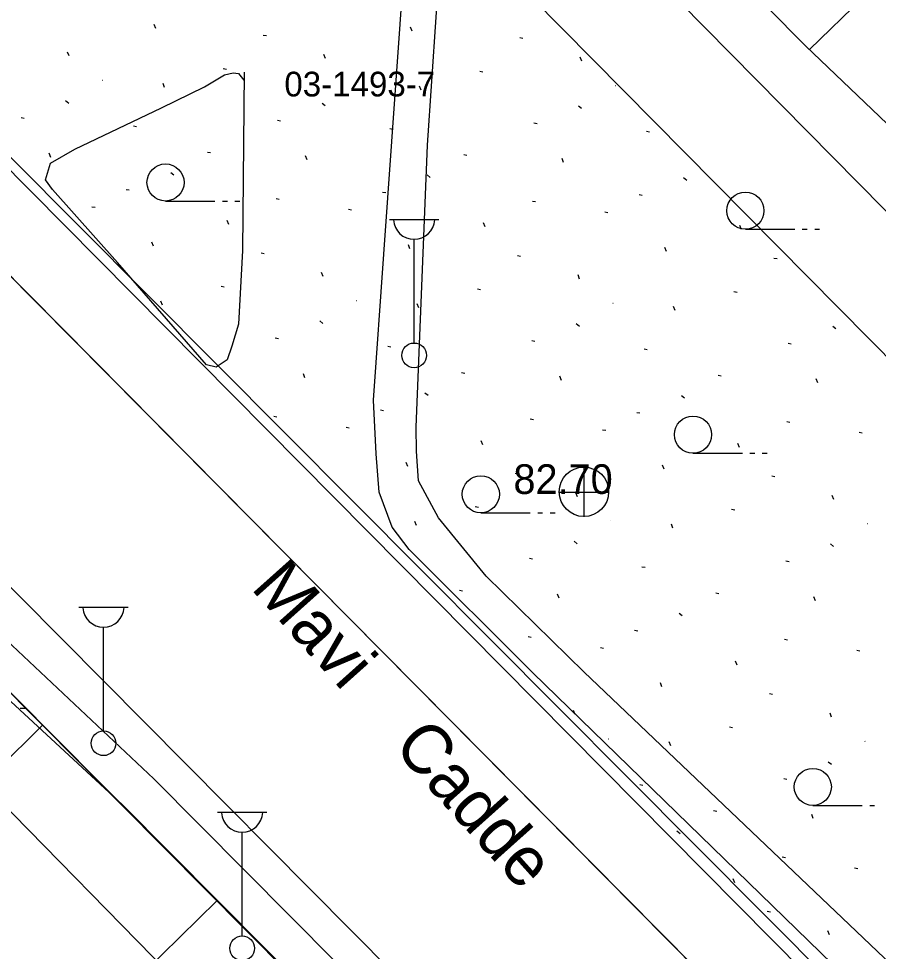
# Model space of a CAD drawing. Extents: x 412225 to 413380, y 4456471 to 4457189.
# Drawn here: x 412345.47 to 412380.23, y 4456938.52 to 4456976.23 of the extents above; entities that cross this region are included whole.
import ezdxf

# ---------------------------------------------------------------- set-up
doc = ezdxf.new("R2010")
doc.units = 0
for name, color, linetype in [('0_HALİHAZIR', 7, 'Continuous'), ('0_KADASTRO', 7, 'Continuous'), ('ADA_KOCEPHE', 7, 'Continuous'), ('Default', 7, 'Continuous'), ('KALDIRIM', 7, 'Continuous'), ('Level 41', 7, 'Continuous'), ('PL_ORGANIZE_SANAYI', 7, 'Continuous')]:
    doc.layers.add(name, color=color, linetype=linetype)

msp = doc.modelspace()

# ---------------------------------------------------------------- linework, layer by layer
at = {"layer": '0_HALİHAZIR'}
for p, q in [((412380.07, 4456977.543), (412377.454, 4456974.98)), ((412351.412, 4456968.858), (412353.412, 4456968.858)), ((412353.712, 4456968.858), (412353.912, 4456968.858)), ((412354.212, 4456968.858), (412354.412, 4456968.858)), ((412360.463, 4456968.117), (412362.463, 4456968.117)), ((412374.857, 4456967.717), (412376.857, 4456967.716)), ((412377.157, 4456967.716), (412377.357, 4456967.716)), ((412377.657, 4456967.716), (412377.857, 4456967.716)), ((412361.463, 4456963.117), (412361.463, 4456967.31)), ((412372.737, 4456958.662), (412374.737, 4456958.662)), ((412375.037, 4456958.662), (412375.237, 4456958.662)), ((412375.537, 4456958.662), (412375.737, 4456958.662)), ((412368.343, 4456956.092), (412368.343, 4456958.092)), ((412367.323, 4456957.082), (412369.323, 4456957.082)), ((412364.16, 4456956.251), (412366.16, 4456956.251)), ((412366.46, 4456956.251), (412366.66, 4456956.251)), ((412366.96, 4456956.251), (412367.16, 4456956.251)), ((412347.905, 4456952.431), (412349.905, 4456952.431)), ((412348.905, 4456947.431), (412348.905, 4456951.624)), ((412345.535, 4456948.352), (412345.735, 4456948.352)), ((412377.581, 4456944.417), (412379.581, 4456944.416)), ((412379.881, 4456944.416), (412380.081, 4456944.416)), ((412353.511, 4456944.141), (412355.511, 4456944.141)), ((412354.511, 4456939.141), (412354.511, 4456943.334))]:
    msp.add_line(p, q, dxfattribs=at)
for points in [[(412364.559, 4456988.91), (412369.327, 4456983.178), (412377.302, 4456975.126), (412390.738, 4456962.288), (412409.437, 4456942.493), (412422.613, 4456929.438), (412434.169, 4456915.9), (412443.007, 4456906.151), (412446.303, 4456903.127)], [(412383.58, 4456935.283), (412368.344, 4456949.804), (412364.375, 4456953.69), (412362.451, 4456956.045), (412361.64, 4456957.546), (412361.556, 4456958.744), (412361.542, 4456959.714), (412362, 4456971.111), (412362.878, 4456984.076)], [(412360.234, 4456966.706), (412361.066, 4456978.306)], [(412349.473, 4456966.368), (412346.849, 4456969.321), (412346.564, 4456969.711), (412346.768, 4456970.388), (412347.745, 4456970.961), (412351.255, 4456972.623), (412352.985, 4456973.471), (412353.799, 4456973.959), (412354.143, 4456974.046), (412354.357, 4456974.017), (412354.584, 4456973.742)], [(412354.587, 4456974.069), (412354.528, 4456966.853), (412354.358, 4456963.875), (412354.092, 4456962.984), (412353.903, 4456962.439), (412353.463, 4456962.136), (412353.067, 4456962.229), (412349.473, 4456966.368)], [(412385.643, 4456930.935), (412366.267, 4456949.783), (412361.263, 4456954.772), (412360.576, 4456955.666), (412360.046, 4456957.088), (412359.925, 4456958.631), (412359.827, 4456960.8), (412360.234, 4456966.706)], [(412340.461, 4456952.961), (412341.05, 4456953.305), (412341.44, 4456953.425), (412342.012, 4456953.384), (412342.339, 4456953.291), (412342.637, 4456952.986), (412344.981, 4456951.095), (412350.936, 4456945.49), (412360.124, 4456936.229), (412372.807, 4456923.414), (412388.747, 4456907.548), (412394.442, 4456901.858), (412397.039, 4456899.351), (412397.651, 4456898.789), (412397.902, 4456898.401), (412398.005, 4456898.011), (412398.01, 4456897.669), (412397.477, 4456896.209)], [(412340.461, 4456952.961), (412349.671, 4456944.435), (412365.051, 4456928.952), (412385.546, 4456908.406), (412397.477, 4456896.209)]]:
    msp.add_lwpolyline(points, dxfattribs=at)
for centre, radius in [((412351.412, 4456969.608), 0.75), ((412374.857, 4456968.467), 0.75), ((412361.463, 4456962.617), 0.5), ((412372.737, 4456959.412), 0.75), ((412364.16, 4456957.001), 0.75), ((412368.328, 4456957.1), 1), ((412348.905, 4456946.931), 0.5), ((412377.581, 4456945.167), 0.75), ((412354.511, 4456938.641), 0.5)]:
    msp.add_circle(centre, radius, dxfattribs=at)
for centre in [(412361.463, 4456968.147), (412348.905, 4456952.461), (412354.511, 4456944.171)]:
    msp.add_arc(centre, 0.837, 183.298, 356.9072, dxfattribs=at)
at = {"layer": '0_KADASTRO'}
for points in [[(412245.621, 4457084.985), (412262.788, 4457087.767), (412498.109, 4456849.333), (412486.377, 4456828.685), (412245.456, 4457070.818)], [(412243.099, 4456868.152), (412335.02, 4456959.17), (412405.36, 4456888.28), (412298.9, 4456782.55), (412242.76, 4456838.938)]]:
    msp.add_lwpolyline(points, dxfattribs=at)
at = {"layer": 'ADA_KOCEPHE'}
for p, q in [((412299.933, 4457044.174), (412519.643, 4456821.8)), ((412299.933, 4457044.174), (412507.885, 4456833.7)), ((412494.937, 4456818.806), (412285.694, 4457030.12)), ((412511.712, 4456801.864), (412285.694, 4457030.12)), ((412335.02, 4456959.17), (412405.36, 4456888.28)), ((412335.02, 4456959.17), (412405.36, 4456888.28))]:
    msp.add_line(p, q, dxfattribs=at)
at = {"layer": 'Default'}
for p, q in [((412513.1, 4456772.743), (412245.17, 4457046.214)), ((412242.844, 4456846.156), (412346.444, 4456947.657)), ((412242.679, 4456831.995), (412353.487, 4456940.558))]:
    msp.add_line(p, q, dxfattribs=at)
at = {"layer": 'KALDIRIM'}
msp.add_line((412509.598, 4456799.736), (412281.429, 4457030.164), dxfattribs=at)
for points in [[(412245.253, 4457053.382), (412266.323, 4457032.279), (412337.147, 4456961.286), (412407.492, 4456890.39), (412481.052, 4456815.891), (412505.085, 4456791.687), (412506.388, 4456790.112), (412510.321, 4456783.97), (412512.973, 4456779.772), (412515.575, 4456774.629), (412518.184, 4456768.139), (412527.355, 4456723.622)], [(412492.963, 4456816.536), (412269.398, 4457042.314)], [(412268.299, 4457030.299), (412337.147, 4456961.286), (412407.492, 4456890.39), (412481.052, 4456815.891), (412505.085, 4456791.687), (412506.388, 4456790.112), (412510.321, 4456783.97), (412512.973, 4456779.772), (412515.575, 4456774.629), (412518.037, 4456768.506)]]:
    msp.add_lwpolyline(points, dxfattribs=at)
at = {"layer": 'Level 41'}
for p, q in [((412351.017, 4456975.836), (412350.953, 4456976)), ((412351.017, 4456975.836), (412350.953, 4456976)), ((412361.384, 4456975.73), (412361.321, 4456975.894)), ((412361.384, 4456975.73), (412361.321, 4456975.894)), ((412355.364, 4456975.571), (412355.49, 4456975.546)), ((412355.364, 4456975.571), (412355.49, 4456975.546)), ((412365.732, 4456975.465), (412365.858, 4456975.44)), ((412365.732, 4456975.465), (412365.858, 4456975.44)), ((412347.51, 4456974.723), (412347.447, 4456974.884)), ((412347.51, 4456974.723), (412347.447, 4456974.884)), ((412357.877, 4456974.616), (412357.815, 4456974.778)), ((412357.877, 4456974.616), (412357.815, 4456974.778)), ((412368.244, 4456974.51), (412368.182, 4456974.672)), ((412368.244, 4456974.51), (412368.182, 4456974.672)), ((412353.747, 4456974.22), (412353.873, 4456974.194)), ((412353.747, 4456974.22), (412353.873, 4456974.194)), ((412364.114, 4456974.114), (412364.24, 4456974.088)), ((412364.114, 4456974.114), (412364.24, 4456974.088)), ((412348.857, 4456973.745), (412348.866, 4456973.743)), ((412348.857, 4456973.745), (412348.866, 4456973.743)), ((412351.374, 4456973.45), (412351.311, 4456973.613)), ((412351.374, 4456973.45), (412351.311, 4456973.613)), ((412359.225, 4456973.639), (412359.233, 4456973.637)), ((412359.225, 4456973.639), (412359.233, 4456973.637)), ((412361.742, 4456973.344), (412361.678, 4456973.506)), ((412361.742, 4456973.344), (412361.678, 4456973.506)), ((412369.592, 4456973.533), (412369.601, 4456973.531)), ((412369.592, 4456973.533), (412369.601, 4456973.531)), ((412347.374, 4456972.921), (412347.5, 4456972.822)), ((412347.374, 4456972.921), (412347.5, 4456972.822)), ((412357.741, 4456972.815), (412357.867, 4456972.715)), ((412357.741, 4456972.815), (412357.867, 4456972.715)), ((412368.109, 4456972.709), (412368.235, 4456972.609)), ((412368.109, 4456972.709), (412368.235, 4456972.609)), ((412345.573, 4456972.235), (412345.699, 4456972.209)), ((412345.573, 4456972.235), (412345.699, 4456972.209)), ((412355.941, 4456972.129), (412356.067, 4456972.103)), ((412355.941, 4456972.129), (412356.067, 4456972.103)), ((412350.118, 4456971.894), (412350.244, 4456971.87)), ((412350.118, 4456971.894), (412350.244, 4456971.87)), ((412360.485, 4456971.788), (412360.611, 4456971.764)), ((412360.485, 4456971.788), (412360.611, 4456971.764)), ((412366.308, 4456972.023), (412366.434, 4456971.997)), ((412366.308, 4456972.023), (412366.434, 4456971.997)), ((412370.853, 4456971.682), (412370.979, 4456971.657)), ((412370.853, 4456971.682), (412370.979, 4456971.657)), ((412346.77, 4456970.625), (412346.707, 4456970.788)), ((412346.77, 4456970.625), (412346.707, 4456970.788)), ((412353.107, 4456970.839), (412353.232, 4456970.814)), ((412353.107, 4456970.839), (412353.232, 4456970.814)), ((412357.137, 4456970.519), (412357.074, 4456970.682)), ((412357.137, 4456970.519), (412357.074, 4456970.682)), ((412363.474, 4456970.733), (412363.599, 4456970.708)), ((412363.474, 4456970.733), (412363.599, 4456970.708)), ((412367.505, 4456970.413), (412367.442, 4456970.576)), ((412367.505, 4456970.413), (412367.442, 4456970.576)), ((412351.623, 4456970.017), (412351.749, 4456969.916)), ((412351.623, 4456970.017), (412351.749, 4456969.916)), ((412361.991, 4456969.911), (412362.117, 4456969.81)), ((412361.991, 4456969.911), (412362.117, 4456969.81)), ((412372.358, 4456969.805), (412372.484, 4456969.704)), ((412372.358, 4456969.805), (412372.484, 4456969.704)), ((412349.821, 4456969.329), (412349.948, 4456969.305)), ((412349.821, 4456969.329), (412349.948, 4456969.305)), ((412360.189, 4456969.223), (412360.315, 4456969.199)), ((412360.189, 4456969.223), (412360.315, 4456969.199)), ((412370.556, 4456969.117), (412370.682, 4456969.092)), ((412370.556, 4456969.117), (412370.682, 4456969.092)), ((412355.881, 4456968.963), (412356.007, 4456968.939)), ((412355.881, 4456968.963), (412356.007, 4456968.939)), ((412366.249, 4456968.857), (412366.375, 4456968.833)), ((412366.249, 4456968.857), (412366.375, 4456968.833)), ((412348.439, 4456968.63), (412348.565, 4456968.604)), ((412348.439, 4456968.63), (412348.565, 4456968.604)), ((412358.806, 4456968.524), (412358.932, 4456968.498)), ((412358.806, 4456968.524), (412358.932, 4456968.498)), ((412369.173, 4456968.418), (412369.299, 4456968.392)), ((412369.173, 4456968.418), (412369.299, 4456968.392)), ((412353.967, 4456967.914), (412353.903, 4456968.077)), ((412353.967, 4456967.914), (412353.903, 4456968.077)), ((412364.335, 4456967.808), (412364.27, 4456967.971)), ((412364.335, 4456967.808), (412364.27, 4456967.971)), ((412374.702, 4456967.702), (412374.638, 4456967.865)), ((412374.702, 4456967.702), (412374.638, 4456967.865)), ((412350.927, 4456967.03), (412350.863, 4456967.194)), ((412350.927, 4456967.03), (412350.863, 4456967.194)), ((412361.294, 4456966.924), (412361.231, 4456967.088)), ((412361.294, 4456966.924), (412361.231, 4456967.088)), ((412371.662, 4456966.818), (412371.598, 4456966.982)), ((412371.662, 4456966.818), (412371.598, 4456966.982)), ((412355.274, 4456966.765), (412355.4, 4456966.741)), ((412355.274, 4456966.765), (412355.4, 4456966.741)), ((412365.642, 4456966.659), (412365.768, 4456966.634)), ((412365.642, 4456966.659), (412365.768, 4456966.634)), ((412376.009, 4456966.553), (412376.135, 4456966.528)), ((412376.009, 4456966.553), (412376.135, 4456966.528)), ((412357.787, 4456965.811), (412357.725, 4456965.973)), ((412357.787, 4456965.811), (412357.725, 4456965.973)), ((412368.154, 4456965.705), (412368.092, 4456965.867)), ((412368.154, 4456965.705), (412368.092, 4456965.867)), ((412353.657, 4456965.414), (412353.783, 4456965.389)), ((412353.657, 4456965.414), (412353.783, 4456965.389)), ((412364.024, 4456965.308), (412364.15, 4456965.283)), ((412364.024, 4456965.308), (412364.15, 4456965.283)), ((412374.392, 4456965.202), (412374.518, 4456965.176)), ((412374.392, 4456965.202), (412374.518, 4456965.176)), ((412351.284, 4456964.644), (412351.221, 4456964.807)), ((412351.284, 4456964.644), (412351.221, 4456964.807)), ((412359.135, 4456964.833), (412359.143, 4456964.831)), ((412359.135, 4456964.833), (412359.143, 4456964.831)), ((412361.651, 4456964.538), (412361.588, 4456964.701)), ((412361.651, 4456964.538), (412361.588, 4456964.701)), ((412369.502, 4456964.727), (412369.511, 4456964.725)), ((412369.502, 4456964.727), (412369.511, 4456964.725)), ((412372.019, 4456964.432), (412371.956, 4456964.595)), ((412372.019, 4456964.432), (412371.956, 4456964.595)), ((412357.651, 4456964.01), (412357.777, 4456963.91)), ((412357.651, 4456964.01), (412357.777, 4456963.91)), ((412368.019, 4456963.904), (412368.145, 4456963.804)), ((412368.019, 4456963.904), (412368.145, 4456963.804)), ((412378.386, 4456963.797), (412378.512, 4456963.698)), ((412378.386, 4456963.797), (412378.512, 4456963.698)), ((412355.85, 4456963.323), (412355.976, 4456963.298)), ((412355.85, 4456963.323), (412355.976, 4456963.298)), ((412366.218, 4456963.217), (412366.344, 4456963.192)), ((412366.218, 4456963.217), (412366.344, 4456963.192)), ((412376.585, 4456963.111), (412376.711, 4456963.085)), ((412376.585, 4456963.111), (412376.711, 4456963.085)), ((412360.395, 4456962.983), (412360.521, 4456962.958)), ((412360.395, 4456962.983), (412360.521, 4456962.958)), ((412370.763, 4456962.877), (412370.889, 4456962.852)), ((412370.763, 4456962.877), (412370.889, 4456962.852)), ((412353.137, 4456962.009), (412353.142, 4456962.008)), ((412353.137, 4456962.009), (412353.142, 4456962.008)), ((412357.047, 4456961.713), (412356.984, 4456961.876)), ((412357.047, 4456961.713), (412356.984, 4456961.876)), ((412363.384, 4456961.928), (412363.509, 4456961.902)), ((412363.384, 4456961.928), (412363.509, 4456961.902)), ((412367.415, 4456961.607), (412367.351, 4456961.77)), ((412367.415, 4456961.607), (412367.351, 4456961.77)), ((412373.752, 4456961.822), (412373.877, 4456961.796)), ((412373.752, 4456961.822), (412373.877, 4456961.796)), ((412377.782, 4456961.501), (412377.719, 4456961.664)), ((412377.782, 4456961.501), (412377.719, 4456961.664)), ((412361.901, 4456961.105), (412362.027, 4456961.004)), ((412361.901, 4456961.105), (412362.027, 4456961.004)), ((412372.268, 4456960.999), (412372.394, 4456960.898)), ((412372.268, 4456960.999), (412372.394, 4456960.898)), ((412360.099, 4456960.418), (412360.225, 4456960.393)), ((412360.099, 4456960.418), (412360.225, 4456960.393)), ((412355.791, 4456960.158), (412355.917, 4456960.133)), ((412355.791, 4456960.158), (412355.917, 4456960.133)), ((412366.159, 4456960.052), (412366.285, 4456960.027)), ((412366.159, 4456960.052), (412366.285, 4456960.027)), ((412370.466, 4456960.312), (412370.592, 4456960.287)), ((412370.466, 4456960.312), (412370.592, 4456960.287)), ((412358.716, 4456959.718), (412358.842, 4456959.692)), ((412358.716, 4456959.718), (412358.842, 4456959.692)), ((412369.083, 4456959.612), (412369.209, 4456959.586)), ((412369.083, 4456959.612), (412369.209, 4456959.586)), ((412376.526, 4456959.946), (412376.652, 4456959.921)), ((412376.526, 4456959.946), (412376.652, 4456959.921)), ((412379.451, 4456959.506), (412379.577, 4456959.48)), ((412379.451, 4456959.506), (412379.577, 4456959.48)), ((412364.244, 4456959.002), (412364.18, 4456959.165)), ((412364.244, 4456959.002), (412364.18, 4456959.165)), ((412374.612, 4456958.896), (412374.548, 4456959.059)), ((412374.612, 4456958.896), (412374.548, 4456959.059)), ((412361.204, 4456958.119), (412361.141, 4456958.283)), ((412361.204, 4456958.119), (412361.141, 4456958.283)), ((412371.571, 4456958.013), (412371.508, 4456958.177)), ((412371.571, 4456958.013), (412371.508, 4456958.177)), ((412365.551, 4456957.854), (412365.678, 4456957.829)), ((412365.551, 4456957.854), (412365.678, 4456957.829)), ((412375.919, 4456957.748), (412376.045, 4456957.723)), ((412375.919, 4456957.748), (412376.045, 4456957.723)), ((412368.064, 4456956.899), (412368.002, 4456957.061)), ((412368.064, 4456956.899), (412368.002, 4456957.061)), ((412378.432, 4456956.793), (412378.369, 4456956.955)), ((412378.432, 4456956.793), (412378.369, 4456956.955)), ((412363.934, 4456956.503), (412364.06, 4456956.477)), ((412363.934, 4456956.503), (412364.06, 4456956.477)), ((412374.301, 4456956.397), (412374.427, 4456956.371)), ((412374.301, 4456956.397), (412374.427, 4456956.371)), ((412361.561, 4456955.732), (412361.498, 4456955.895)), ((412361.561, 4456955.732), (412361.498, 4456955.895)), ((412369.412, 4456955.922), (412369.421, 4456955.92)), ((412369.412, 4456955.922), (412369.421, 4456955.92)), ((412371.929, 4456955.626), (412371.865, 4456955.789)), ((412371.929, 4456955.626), (412371.865, 4456955.789)), ((412379.779, 4456955.816), (412379.788, 4456955.814)), ((412379.779, 4456955.816), (412379.788, 4456955.814)), ((412367.928, 4456955.098), (412368.055, 4456954.998)), ((412367.928, 4456955.098), (412368.055, 4456954.998)), ((412378.296, 4456954.992), (412378.422, 4456954.892)), ((412378.296, 4456954.992), (412378.422, 4456954.892)), ((412366.128, 4456954.412), (412366.254, 4456954.386)), ((412366.128, 4456954.412), (412366.254, 4456954.386)), ((412370.673, 4456954.071), (412370.799, 4456954.046)), ((412370.673, 4456954.071), (412370.799, 4456954.046)), ((412376.495, 4456954.306), (412376.621, 4456954.28)), ((412376.495, 4456954.306), (412376.621, 4456954.28)), ((412363.294, 4456953.122), (412363.419, 4456953.096)), ((412363.294, 4456953.122), (412363.419, 4456953.096)), ((412367.325, 4456952.802), (412367.261, 4456952.964)), ((412367.325, 4456952.802), (412367.261, 4456952.964)), ((412373.661, 4456953.016), (412373.786, 4456952.99)), ((412373.661, 4456953.016), (412373.786, 4456952.99)), ((412377.692, 4456952.695), (412377.629, 4456952.858)), ((412377.692, 4456952.695), (412377.629, 4456952.858)), ((412372.178, 4456952.193), (412372.304, 4456952.093)), ((412372.178, 4456952.193), (412372.304, 4456952.093)), ((412370.376, 4456951.506), (412370.502, 4456951.481)), ((412370.376, 4456951.506), (412370.502, 4456951.481)), ((412366.068, 4456951.246), (412366.194, 4456951.221)), ((412366.068, 4456951.246), (412366.194, 4456951.221)), ((412376.436, 4456951.14), (412376.562, 4456951.115)), ((412376.436, 4456951.14), (412376.562, 4456951.115)), ((412368.993, 4456950.807), (412369.119, 4456950.781)), ((412368.993, 4456950.807), (412369.119, 4456950.781)), ((412379.361, 4456950.7), (412379.487, 4456950.675)), ((412379.361, 4456950.7), (412379.487, 4456950.675)), ((412374.522, 4456950.091), (412374.457, 4456950.254)), ((412374.522, 4456950.091), (412374.457, 4456950.254)), ((412371.481, 4456949.207), (412371.418, 4456949.371)), ((412371.481, 4456949.207), (412371.418, 4456949.371)), ((412375.829, 4456948.942), (412375.955, 4456948.917)), ((412375.829, 4456948.942), (412375.955, 4456948.917)), ((412367.974, 4456948.094), (412367.912, 4456948.256)), ((412367.974, 4456948.094), (412367.912, 4456948.256)), ((412378.342, 4456947.988), (412378.279, 4456948.149)), ((412378.342, 4456947.988), (412378.279, 4456948.149)), ((412374.211, 4456947.591), (412374.337, 4456947.565)), ((412374.211, 4456947.591), (412374.337, 4456947.565)), ((412369.322, 4456947.116), (412369.33, 4456947.114)), ((412369.322, 4456947.116), (412369.33, 4456947.114)), ((412371.839, 4456946.821), (412371.775, 4456946.984)), ((412371.839, 4456946.821), (412371.775, 4456946.984)), ((412379.689, 4456947.01), (412379.698, 4456947.008)), ((412379.689, 4456947.01), (412379.698, 4456947.008)), ((412378.206, 4456946.186), (412378.332, 4456946.087)), ((412378.206, 4456946.186), (412378.332, 4456946.087)), ((412376.405, 4456945.5), (412376.531, 4456945.474)), ((412376.405, 4456945.5), (412376.531, 4456945.474)), ((412370.582, 4456945.266), (412370.709, 4456945.241)), ((412370.582, 4456945.266), (412370.709, 4456945.241)), ((412373.571, 4456944.211), (412373.696, 4456944.185)), ((412373.571, 4456944.211), (412373.696, 4456944.185)), ((412377.602, 4456943.89), (412377.539, 4456944.053)), ((412377.602, 4456943.89), (412377.539, 4456944.053)), ((412372.088, 4456943.388), (412372.214, 4456943.287)), ((412372.088, 4456943.388), (412372.214, 4456943.287)), ((412376.346, 4456942.335), (412376.472, 4456942.31)), ((412376.346, 4456942.335), (412376.472, 4456942.31)), ((412379.271, 4456941.895), (412379.397, 4456941.869)), ((412379.271, 4456941.895), (412379.397, 4456941.869)), ((412374.432, 4456941.285), (412374.367, 4456941.448)), ((412374.432, 4456941.285), (412374.367, 4456941.448)), ((412375.739, 4456940.137), (412375.865, 4456940.112)), ((412375.739, 4456940.137), (412375.865, 4456940.112)), ((412378.251, 4456939.182), (412378.189, 4456939.344)), ((412378.251, 4456939.182), (412378.189, 4456939.344))]:
    msp.add_line(p, q, dxfattribs=at)
at = {"layer": 'PL_ORGANIZE_SANAYI'}
msp.add_line((412335.02, 4456959.17), (412405.36, 4456888.28), dxfattribs=at)

# ---------------------------------------------------------------- texts
at = {"layer": '0_HALİHAZIR'}
for s, height, p in [('03-1493-7', 1, (412356.217, 4456973.087)), ('82.70', 1.2, (412365.478, 4456957.013))]:
    msp.add_text(s, height=height, dxfattribs=at).set_placement(p)
msp.add_text('Mavi    Cadde', height=2, rotation=311.8163, dxfattribs=at).set_placement((412354.823, 4456953.2))
at = {"layer": '0_KADASTRO'}
msp.add_text('03-1493-7', height=1, dxfattribs=at).set_placement((412356.217, 4456973.087))

doc.saveas('drawing.dxf')
